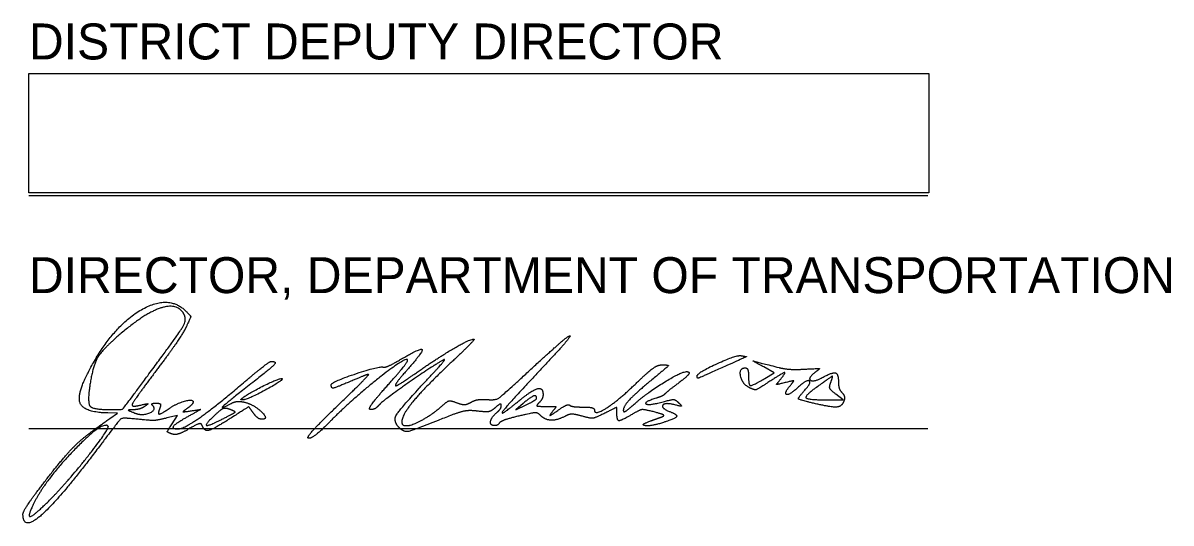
# Model space of a CAD drawing. Extents: x 0 to 34, y 0 to 22.
# Drawn here: x 24.504 to 28.975, y 7.28 to 9.227 of the extents above; entities that cross this region are included whole.
import ezdxf

# ---------------------------------------------------------------- set-up
doc = ezdxf.new("R2010")
doc.units = 0
doc.layers.add('GM_X_Adjacent_County', color=7, linetype='Continuous')
doc.layers.add('GM_X_Township', color=7, linetype='Continuous')

msp = doc.modelspace()

# ---------------------------------------------------------------- linework, layer by layer
at = {"layer": 'GM_X_Adjacent_County'}
for p, q in [((24.9902, 7.8533), (24.9902, 7.8533)), ((27.1295, 7.8524), (27.1295, 7.8524)), ((25.3555, 7.7634), (25.3555, 7.7634)), ((25.7273, 7.7344), (25.7273, 7.7344)), ((26.5045, 7.7654), (26.5045, 7.7654)), ((27.582, 7.7462), (27.582, 7.7462)), ((25.3107, 7.7218), (25.3107, 7.7218)), ((24.6198, 7.3807), (24.6198, 7.3807)), ((24.5045, 7.3139), (24.5045, 7.3139))]:
    msp.add_line(p, q, dxfattribs=at)
for points in [[(27.3933, 7.8428), (27.4297, 7.8644), (27.3889, 7.8873)], [(27.642, 7.7593), (27.6982, 7.7594), (27.6695, 7.7815)], [(26.4527, 7.7457), (26.4232, 7.7201), (26.4638, 7.7398)], [(24.8425, 7.6863), (24.8732, 7.7075), (24.8354, 7.7082)], [(25.0855, 7.6665), (25.1067, 7.6988), (25.0649, 7.6887)]]:
    msp.add_lwpolyline(points, dxfattribs=at)
for points in [[(24.7789, 7.904), (24.8651, 8.0544), (25.0732, 8.1704), (25.1389, 8.1048)], [(25.1299, 8.0956), (25.104, 8.1376), (24.9779, 8.0964), (24.8825, 8.0148)], [(24.9902, 7.8533), (25.1115, 8.0167), (25.144, 8.0729), (25.1299, 8.0956)], [(25.1389, 8.1048), (25.1577, 8.086), (25.1577, 8.0809), (25.1394, 8.0425)], [(24.8825, 8.0148), (24.8159, 7.9578), (24.7771, 7.8937), (24.766, 7.8224)], [(25.1394, 8.0425), (25.1284, 8.0195), (25.0767, 7.944), (25.0245, 7.8746)], [(26.4869, 7.8829), (26.5619, 7.952), (26.6279, 8.0086), (26.6336, 8.0087)], [(26.6336, 8.0087), (26.6394, 8.0088), (26.5873, 7.9486), (26.518, 7.875)], [(26.0326, 7.8625), (26.1131, 7.9191), (26.2445, 7.9963), (26.2602, 7.9963)], [(26.2602, 7.9963), (26.265, 7.9963), (26.2237, 7.9537), (26.1684, 7.9016)], [(26.0017, 7.9158), (25.9921, 7.9254), (25.7824, 7.7584), (25.7045, 7.6792)], [(26.142, 7.9153), (26.0929, 7.8875), (25.9046, 7.7553), (25.8914, 7.7394)], [(25.908, 7.8868), (25.9136, 7.885), (25.9431, 7.8981), (25.9736, 7.916)], [(25.9239, 7.8154), (25.9702, 7.8671), (26.0052, 7.9123), (26.0017, 7.9158)], [(25.9736, 7.916), (26.0524, 7.9622), (26.0646, 7.9489), (26.0054, 7.8816)], [(26.0768, 7.8364), (26.123, 7.8856), (26.1523, 7.9211), (26.142, 7.9153)], [(27.1295, 7.8524), (27.1295, 7.8648), (27.2823, 7.9351), (27.3012, 7.9314)], [(27.3012, 7.9314), (27.3219, 7.9274), (27.3226, 7.9278), (27.201, 7.8732)], [(24.8354, 7.7082), (24.7375, 7.7099), (24.7141, 7.791), (24.7789, 7.904)], [(25.0245, 7.8746), (24.9722, 7.8053), (24.9295, 7.7446), (24.9295, 7.7398)], [(25.369, 7.8305), (25.4194, 7.8734), (25.4649, 7.9086), (25.4701, 7.9087)], [(25.4701, 7.9087), (25.495, 7.9092), (25.4716, 7.8836), (25.3857, 7.8163)], [(25.7047, 7.8182), (25.7049, 7.8288), (25.8923, 7.8919), (25.908, 7.8868)], [(26.0054, 7.8816), (25.9774, 7.8498), (25.9545, 7.8201), (25.9545, 7.8157)], [(26.1684, 7.9016), (26.0687, 7.8079), (25.9795, 7.6998), (25.9795, 7.6728)], [(26.3119, 7.7605), (26.3453, 7.7577), (26.3688, 7.7741), (26.4869, 7.8829)], [(26.518, 7.875), (26.3885, 7.7375), (26.3564, 7.6902), (26.4386, 7.7579)], [(26.8763, 7.7355), (26.93, 7.7843), (27.0769, 7.8743), (27.0938, 7.8687)], [(26.8951, 7.8267), (26.9403, 7.8705), (26.9774, 7.8961), (26.9951, 7.8958)], [(26.9951, 7.8958), (27.0194, 7.8953), (27.0156, 7.889), (26.967, 7.8489)], [(27.0938, 7.8687), (27.1022, 7.8659), (27.087, 7.8471), (27.0599, 7.8269)], [(27.201, 7.8732), (27.1385, 7.8451), (27.1295, 7.8425), (27.1295, 7.8524)], [(27.3305, 7.8083), (27.304, 7.8225), (27.293, 7.8838), (27.317, 7.8838)], [(27.317, 7.8838), (27.3238, 7.8838), (27.3295, 7.8698), (27.3295, 7.8526)], [(27.3889, 7.8873), (27.3461, 7.9114), (27.3452, 7.9115), (27.4482, 7.8851)], [(27.4482, 7.8851), (27.4688, 7.8798), (27.5138, 7.877), (27.5482, 7.8789)], [(27.5482, 7.8789), (27.6031, 7.882), (27.608, 7.8804), (27.5881, 7.8656)], [(24.844, 7.7213), (24.8907, 7.7213), (24.8953, 7.7255), (24.9902, 7.8533)], [(25.1076, 7.6463), (25.1307, 7.6463), (25.2567, 7.7352), (25.369, 7.8305)], [(25.3555, 7.7634), (25.3759, 7.7813), (25.5079, 7.847), (25.5131, 7.8419)], [(25.5131, 7.8419), (25.5193, 7.8357), (25.3767, 7.7588), (25.359, 7.7588)], [(25.7857, 7.8338), (25.7231, 7.807), (25.7044, 7.8034), (25.7047, 7.8182)], [(25.7273, 7.7344), (25.7983, 7.8028), (25.8537, 7.8588), (25.8502, 7.8588)], [(25.8502, 7.8588), (25.8468, 7.8588), (25.8178, 7.8476), (25.7857, 7.8338)], [(25.9697, 7.6508), (25.9445, 7.676), (25.9734, 7.7261), (26.0768, 7.8364)], [(25.9545, 7.8157), (25.9545, 7.8112), (25.9896, 7.8323), (26.0326, 7.8625)], [(26.7295, 7.7198), (26.7295, 7.697), (26.8248, 7.7585), (26.8951, 7.8267)], [(26.967, 7.8489), (26.8929, 7.788), (26.842, 7.7344), (26.842, 7.7177)], [(27.0599, 7.8269), (27.0328, 7.8067), (27.0079, 7.7867), (27.0045, 7.7825)], [(27.3295, 7.8526), (27.3295, 7.8158), (27.3438, 7.8136), (27.3933, 7.8428)], [(27.4052, 7.8266), (27.3652, 7.8001), (27.3519, 7.7969), (27.3305, 7.8083)], [(27.4529, 7.838), (27.4773, 7.8676), (27.4615, 7.8638), (27.4052, 7.8266)], [(27.4723, 7.8263), (27.4392, 7.8181), (27.4374, 7.8192), (27.4529, 7.838)], [(27.4924, 7.8156), (27.507, 7.8332), (27.5047, 7.8344), (27.4723, 7.8263)], [(27.5462, 7.7942), (27.5767, 7.8279), (27.5551, 7.8388), (27.5211, 7.8068)], [(27.5881, 7.8656), (27.5593, 7.8441), (27.5822, 7.8277), (27.6159, 7.8458)], [(27.6497, 7.827), (27.6596, 7.8528), (27.6514, 7.8497), (27.5888, 7.8042)], [(27.6159, 7.8458), (27.6561, 7.8673), (27.6795, 7.8615), (27.6795, 7.8301)], [(27.6695, 7.7815), (27.6491, 7.7972), (27.6434, 7.8104), (27.6497, 7.827)], [(27.6795, 7.8301), (27.6795, 7.8143), (27.6858, 7.795), (27.6936, 7.7872)], [(24.766, 7.8224), (24.7545, 7.7491), (24.776, 7.7213), (24.844, 7.7213)], [(25.3857, 7.8163), (25.2925, 7.7433), (25.271, 7.7218), (25.315, 7.7453)], [(25.8581, 7.7213), (25.8478, 7.7213), (25.8767, 7.7626), (25.9239, 7.8154)], [(26.4386, 7.7579), (26.487, 7.7978), (26.5295, 7.8082), (26.5295, 7.7801)], [(26.5295, 7.7801), (26.5295, 7.7712), (26.5227, 7.7571), (26.5145, 7.7488)], [(27.0045, 7.7825), (27.001, 7.7782), (26.9856, 7.7708), (26.9701, 7.7659)], [(27.5211, 7.8068), (27.4892, 7.7769), (27.4661, 7.7839), (27.4924, 7.8156)], [(27.582, 7.7462), (27.5272, 7.7591), (27.5215, 7.7668), (27.5462, 7.7942)], [(27.5888, 7.8042), (27.5461, 7.7731), (27.5626, 7.7592), (27.642, 7.7593)], [(27.6936, 7.7872), (27.7014, 7.7794), (27.7044, 7.7642), (27.7003, 7.7534)], [(24.9295, 7.7398), (24.9295, 7.735), (24.9449, 7.7347), (24.9638, 7.7391)], [(24.9795, 7.7344), (24.9692, 7.7274), (24.9495, 7.7213), (24.9357, 7.7207)], [(24.9399, 7.7081), (24.9698, 7.6961), (25.026, 7.7207), (25.0086, 7.7381)], [(24.9638, 7.7391), (24.9894, 7.745), (24.9934, 7.7438), (24.9795, 7.7344)], [(25.0086, 7.7381), (25.004, 7.7426), (25.0103, 7.7463), (25.0225, 7.7463)], [(25.0225, 7.7463), (25.037, 7.7463), (25.0422, 7.7399), (25.0375, 7.7276)], [(25.0736, 7.7257), (25.1025, 7.7455), (25.167, 7.763), (25.167, 7.7511)], [(25.167, 7.7511), (25.167, 7.7466), (25.1572, 7.7357), (25.1453, 7.727)], [(25.315, 7.7453), (25.3276, 7.752), (25.3515, 7.7541), (25.3681, 7.7499)], [(25.359, 7.7588), (25.3542, 7.7588), (25.3526, 7.7609), (25.3555, 7.7634)], [(25.3681, 7.7499), (25.4042, 7.7408), (25.4625, 7.6838), (25.4358, 7.6838)], [(25.617, 7.6095), (25.6067, 7.6097), (25.6563, 7.6659), (25.7273, 7.7344)], [(25.8914, 7.7394), (25.8831, 7.7295), (25.8682, 7.7213), (25.8581, 7.7213)], [(25.9975, 7.6588), (26.0192, 7.6588), (26.1006, 7.7041), (26.137, 7.7364)], [(26.137, 7.7364), (26.1573, 7.7544), (26.1701, 7.757), (26.1939, 7.748)], [(26.1939, 7.748), (26.2141, 7.7403), (26.2329, 7.741), (26.2489, 7.7501)], [(26.2489, 7.7501), (26.2623, 7.7576), (26.2906, 7.7623), (26.3119, 7.7605)], [(26.367, 7.7373), (26.367, 7.7444), (26.3568, 7.741), (26.3444, 7.7298)], [(26.3482, 7.7088), (26.3585, 7.7174), (26.367, 7.7302), (26.367, 7.7373)], [(26.5045, 7.7654), (26.5045, 7.7789), (26.4804, 7.7697), (26.4527, 7.7457)], [(26.4638, 7.7398), (26.4862, 7.7506), (26.5045, 7.7622), (26.5045, 7.7654)], [(26.5145, 7.7488), (26.5028, 7.7372), (26.5087, 7.7338), (26.541, 7.7338)], [(26.541, 7.7338), (26.5785, 7.7338), (26.5809, 7.7318), (26.5654, 7.7125)], [(26.5871, 7.7183), (26.6085, 7.7333), (26.6293, 7.7424), (26.6332, 7.7385)], [(26.6332, 7.7385), (26.6371, 7.7346), (26.6604, 7.7313), (26.6849, 7.7313)], [(26.842, 7.7177), (26.842, 7.7103), (26.8574, 7.7183), (26.8763, 7.7355)], [(26.9701, 7.7659), (26.9206, 7.7505), (26.9401, 7.7368), (26.9919, 7.7506)], [(26.9919, 7.7506), (27.0302, 7.7609), (27.0455, 7.7603), (27.0575, 7.748)], [(27.0388, 7.7406), (27.0021, 7.7496), (26.9889, 7.7266), (27.0232, 7.7134)], [(27.0575, 7.748), (27.0702, 7.7351), (27.0666, 7.7337), (27.0388, 7.7406)], [(27.7003, 7.7534), (27.6922, 7.7324), (27.651, 7.7298), (27.582, 7.7462)], [(24.9357, 7.7207), (24.9133, 7.7199), (24.9138, 7.7185), (24.9399, 7.7081)], [(25.0649, 7.6887), (25.0246, 7.679), (25.0023, 7.6786), (24.9237, 7.6864)], [(25.0375, 7.7276), (25.0285, 7.7043), (25.0414, 7.7037), (25.0736, 7.7257)], [(25.1522, 7.697), (25.1011, 7.6688), (25.0814, 7.6463), (25.1076, 7.6463)], [(25.1453, 7.727), (25.1264, 7.7132), (25.1284, 7.7119), (25.161, 7.7168)], [(25.161, 7.7168), (25.1977, 7.7224), (25.1976, 7.7221), (25.1522, 7.697)], [(25.3165, 7.6898), (25.2476, 7.6454), (25.2101, 7.6357), (25.202, 7.66)], [(25.2576, 7.7052), (25.2133, 7.6647), (25.2246, 7.6558), (25.2826, 7.6854)], [(25.3107, 7.7218), (25.2935, 7.7281), (25.277, 7.723), (25.2576, 7.7052)], [(25.2826, 7.6854), (25.329, 7.7091), (25.3325, 7.7137), (25.3107, 7.7218)], [(25.4011, 7.7085), (25.3843, 7.7326), (25.3822, 7.7321), (25.3165, 7.6898)], [(25.4358, 7.6838), (25.4262, 7.6838), (25.4106, 7.6949), (25.4011, 7.7085)], [(26.1693, 7.6982), (26.0233, 7.6406), (25.9882, 7.6322), (25.9697, 7.6508)], [(26.2749, 7.7154), (26.2457, 7.7191), (26.2058, 7.7127), (26.1693, 7.6982)], [(26.3444, 7.7298), (26.3287, 7.7156), (26.3075, 7.7112), (26.2749, 7.7154)], [(26.3412, 7.6588), (26.3229, 7.6588), (26.3274, 7.6916), (26.3482, 7.7088)], [(26.4355, 7.6963), (26.3972, 7.6871), (26.3629, 7.6749), (26.3594, 7.6692)], [(26.5199, 7.6984), (26.5088, 7.7096), (26.4887, 7.7091), (26.4355, 7.6963)], [(26.6162, 7.6959), (26.5854, 7.6795), (26.5376, 7.6807), (26.5199, 7.6984)], [(26.5654, 7.7125), (26.5533, 7.6975), (26.5598, 7.6992), (26.5871, 7.7183)], [(26.6807, 7.696), (26.6538, 7.7037), (26.6307, 7.7037), (26.6162, 7.6959)], [(26.7698, 7.7073), (26.7324, 7.6889), (26.7138, 7.6865), (26.6807, 7.696)], [(26.6849, 7.7313), (26.7094, 7.7313), (26.7295, 7.7262), (26.7295, 7.7198)], [(26.817, 7.7073), (26.817, 7.7302), (26.8159, 7.7302), (26.7698, 7.7073)], [(26.8789, 7.7043), (26.8339, 7.6776), (26.817, 7.6785), (26.817, 7.7073)], [(26.9621, 7.7123), (26.9233, 7.7222), (26.9065, 7.7205), (26.8789, 7.7043)], [(26.9482, 7.6773), (26.962, 7.6822), (26.9817, 7.6893), (26.992, 7.6931)], [(26.992, 7.6931), (27.0034, 7.6972), (26.9917, 7.7047), (26.9621, 7.7123)], [(27.0232, 7.7134), (27.0538, 7.7016), (27.0449, 7.6867), (26.9981, 7.6713)], [(24.8354, 7.6571), (24.8145, 7.678), (24.596, 7.4523), (24.5497, 7.362)], [(24.5916, 7.4441), (24.6692, 7.5446), (24.7493, 7.6219), (24.8425, 7.6863)], [(24.6198, 7.3807), (24.6874, 7.4498), (24.8431, 7.6494), (24.8354, 7.6571)], [(24.9237, 7.6864), (24.8903, 7.6897), (24.8786, 7.6792), (24.8019, 7.5776)], [(25.0843, 7.6264), (25.0661, 7.6334), (25.0662, 7.637), (25.0855, 7.6665)], [(25.1508, 7.6462), (25.1252, 7.6311), (25.0953, 7.6222), (25.0843, 7.6264)], [(25.202, 7.66), (25.1991, 7.6686), (25.1799, 7.6634), (25.1508, 7.6462)], [(25.7045, 7.6792), (25.6667, 7.6407), (25.6273, 7.6094), (25.617, 7.6095)], [(25.9795, 7.6728), (25.9795, 7.6651), (25.9876, 7.6588), (25.9975, 7.6588)], [(26.3594, 7.6692), (26.3559, 7.6635), (26.3477, 7.6588), (26.3412, 7.6588)], [(26.9981, 7.6713), (26.9515, 7.6559), (26.9042, 7.6617), (26.9482, 7.6773)], [(24.8019, 7.5776), (24.6496, 7.3755), (24.5045, 7.2469), (24.5045, 7.3139)], [(24.5045, 7.3139), (24.5045, 7.3235), (24.5437, 7.3821), (24.5916, 7.4441)], [(24.5497, 7.362), (24.5184, 7.301), (24.55, 7.3095), (24.6198, 7.3807)]]:
    msp.add_open_spline(points, degree=2, dxfattribs=at)
at = {"layer": 'GM_X_Township'}
for p, q in [((24.5279, 8.555), (28.0279, 8.555)), ((24.5279, 7.6482), (28.0279, 7.6482))]:
    msp.add_line(p, q, dxfattribs=at)
msp.add_lwpolyline([(24.5279, 8.565), (24.5279, 9.0299), (28.032, 9.0299), (28.032, 8.565)], close=True, dxfattribs=at)

# ---------------------------------------------------------------- texts
at = {"layer": 'GM_X_Adjacent_County'}
for s, p in [('DISTRICT DEPUTY DIRECTOR', (24.5279, 9.085)), ('DIRECTOR, DEPARTMENT OF TRANSPORTATION', (24.5279, 8.175))]:
    msp.add_text(s, height=0.14, dxfattribs=at).set_placement(p)

doc.saveas('drawing.dxf')
